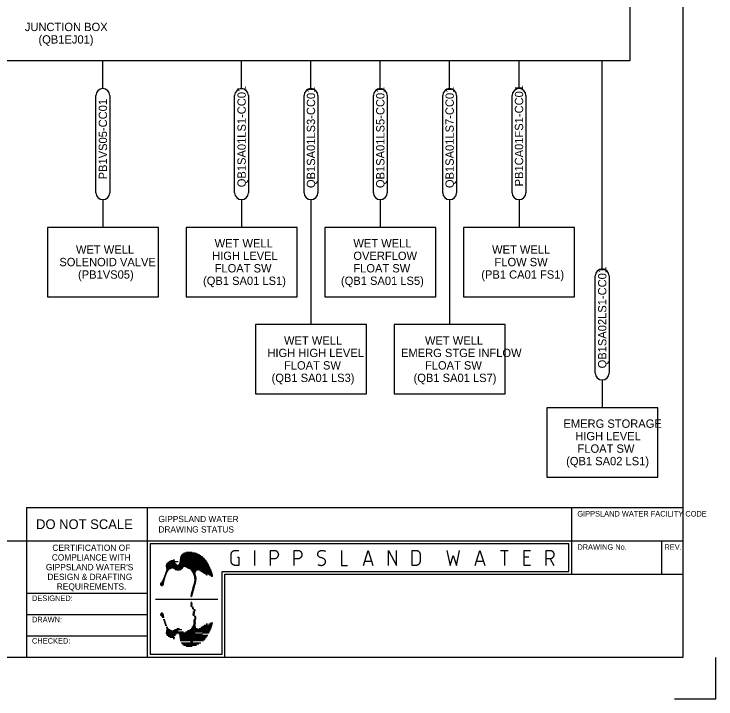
# Model space of a CAD drawing. Extents: x 0 to 841, y 0 to 594.
# Drawn here: x 588 to 841, y 0 to 246.9 of the extents above; entities that cross this region are included whole.
import ezdxf

# ---------------------------------------------------------------- set-up
doc = ezdxf.new("R2010")
doc.units = 0
doc.layers.add('A1BORDER', color=7, linetype='Continuous')
doc.layers.add('INSTALLED', color=7, linetype='Continuous')

msp = doc.modelspace()

# ---------------------------------------------------------------- linework, layer by layer
at = {"layer": 'A1BORDER'}
for p, q in [((829, 581), (829, 15)), ((592.5, 69), (592.5, 15)), ((592.5, 69), (829, 69)), ((636, 69), (636, 15)), ((789, 45), (789, 69)), ((28, 57), (829, 57)), ((637, 56), (788, 56)), ((637, 56), (637, 16)), ((788, 46), (788, 56)), ((821.5, 45), (821.5, 57)), ((647.88, 50.72), (656.5, 50.72)), ((647.91, 50.92), (656.3, 50.92)), ((647.96, 51.12), (656.08, 51.12)), ((648.03, 51.32), (655.85, 51.32)), ((648.12, 51.52), (655.59, 51.52)), ((648.23, 51.72), (655.31, 51.72)), ((648.37, 51.92), (655, 51.92)), ((648.53, 52.12), (654.64, 52.12)), ((648.74, 52.32), (654.24, 52.32)), ((649.02, 52.52), (653.76, 52.52)), ((649.39, 52.72), (653.15, 52.72)), ((650.01, 52.92), (652.2, 52.92)), ((642.73, 48.12), (658.25, 48.12)), ((642.75, 48.32), (646.79, 48.32)), ((642.81, 48.52), (646.55, 48.52)), ((642.9, 48.72), (646.37, 48.72)), ((643.04, 48.92), (646.16, 48.92)), ((643.26, 49.12), (645.9, 49.12)), ((643.54, 49.32), (645.57, 49.32)), ((643.85, 49.52), (647.09, 49.52)), ((644.18, 49.72), (645.89, 49.72)), ((644.54, 49.92), (645.36, 49.92)), ((645.37, 50.12), (645.86, 50.12)), ((647.19, 48.32), (658.14, 48.32)), ((647.42, 48.52), (658.03, 48.52)), ((647.54, 48.72), (657.92, 48.72)), ((647.61, 48.92), (657.8, 48.92)), ((647.63, 49.12), (657.68, 49.12)), ((647.66, 49.32), (657.57, 49.32)), ((647.69, 49.52), (657.44, 49.52)), ((647.71, 49.72), (657.31, 49.72)), ((647.75, 49.92), (657.17, 49.92)), ((647.78, 50.12), (657.02, 50.12)), ((647.81, 50.32), (656.86, 50.32)), ((647.85, 50.52), (656.69, 50.52)), ((642.65, 45.72), (643.2, 45.72)), ((642.72, 45.92), (643.3, 45.92)), ((642.74, 47.92), (658.35, 47.92)), ((642.79, 47.72), (649.08, 47.72)), ((642.79, 46.12), (643.4, 46.12)), ((642.83, 47.52), (648.95, 47.52)), ((642.84, 46.32), (643.5, 46.32)), ((642.85, 47.31), (644.88, 47.31)), ((642.87, 47.12), (644.57, 47.12)), ((642.87, 46.52), (643.6, 46.52)), ((642.88, 46.92), (644.23, 46.92)), ((642.88, 46.72), (643.83, 46.72)), ((645.14, 47.31), (648.83, 47.31)), ((645.49, 47.12), (648.67, 47.12)), ((645.76, 46.92), (648.42, 46.92)), ((646.05, 46.72), (648.11, 46.72)), ((646.62, 46.52), (647.67, 46.52)), ((649.72, 47.72), (658.45, 47.72)), ((650.12, 47.52), (658.55, 47.52)), ((650.48, 47.31), (658.64, 47.31)), ((650.87, 47.12), (658.73, 47.12)), ((651.36, 46.92), (658.82, 46.92)), ((651.76, 46.72), (658.9, 46.72)), ((651.88, 46.52), (654.15, 46.52)), ((651.99, 46.32), (653.71, 46.32)), ((652.1, 46.12), (653.52, 46.12)), ((652.2, 45.92), (653.4, 45.92)), ((652.31, 45.72), (653.33, 45.72)), ((654.57, 46.52), (658.99, 46.52)), ((655, 46.32), (659.07, 46.32)), ((655.31, 46.12), (659.14, 46.12)), ((655.62, 45.92), (659.22, 45.92)), ((655.93, 45.72), (659.29, 45.72)), ((663, 46), (788, 46)), ((663, 16), (663, 46)), ((641.64, 43.12), (642.25, 43.12)), ((641.73, 43.32), (642.3, 43.32)), ((641.82, 43.51), (642.35, 43.51)), ((641.91, 43.72), (642.41, 43.72)), ((641.99, 43.92), (642.48, 43.92)), ((642.06, 44.12), (642.55, 44.12)), ((642.13, 44.32), (642.62, 44.32)), ((642.21, 44.52), (642.69, 44.52)), ((642.28, 44.72), (642.76, 44.72)), ((642.35, 44.92), (642.83, 44.92)), ((642.43, 45.12), (642.9, 45.12)), ((642.5, 45.32), (643, 45.32)), ((642.57, 45.52), (643.1, 45.52)), ((652.41, 45.52), (653.31, 45.52)), ((652.5, 45.32), (653.34, 45.32)), ((652.6, 45.12), (653.38, 45.12)), ((652.69, 44.92), (653.41, 44.92)), ((652.78, 44.72), (653.44, 44.72)), ((652.83, 44.52), (653.48, 44.52)), ((652.86, 44.32), (653.53, 44.32)), ((652.89, 44.12), (653.57, 44.12)), ((652.91, 43.92), (653.62, 43.92)), ((652.94, 43.72), (653.67, 43.72)), ((652.97, 43.51), (653.71, 43.51)), ((653, 43.32), (653.69, 43.32)), ((653.02, 43.12), (653.67, 43.12)), ((656.24, 45.52), (659.35, 45.52)), ((656.55, 45.32), (659.42, 45.32)), ((656.86, 45.12), (657.74, 45.12)), ((657.17, 44.92), (657.68, 44.92)), ((657.51, 44.72), (657.54, 44.72)), ((657.91, 45.12), (659.48, 45.12)), ((658.19, 44.92), (659.54, 44.92)), ((658.47, 44.72), (659.59, 44.72)), ((658.75, 44.52), (659.58, 44.52)), ((659.02, 44.32), (659.47, 44.32)), ((664, 45), (829, 45)), ((664, 15), (664, 45)), ((640.62, 41.32), (641.88, 41.32)), ((640.63, 41.52), (641.93, 41.52)), ((640.72, 41.12), (641.73, 41.12)), ((640.73, 41.72), (641.95, 41.72)), ((640.9, 41.92), (641.97, 41.92)), ((641.03, 40.92), (641.43, 40.92)), ((641.1, 42.12), (642, 42.12)), ((641.25, 42.31), (642.04, 42.31)), ((641.37, 42.52), (642.09, 42.52)), ((641.46, 42.72), (642.15, 42.72)), ((641.55, 42.92), (642.2, 42.92)), ((652.47, 40.52), (653.1, 40.52)), ((652.52, 40.72), (653.15, 40.72)), ((652.57, 40.92), (653.2, 40.92)), ((652.63, 41.12), (653.26, 41.12)), ((652.68, 41.32), (653.31, 41.32)), ((652.74, 41.52), (653.37, 41.52)), ((652.79, 41.72), (653.41, 41.72)), ((652.85, 41.92), (653.45, 41.92)), ((652.9, 42.12), (653.49, 42.12)), ((652.95, 42.31), (653.53, 42.31)), ((652.99, 42.52), (653.57, 42.52)), ((653.03, 42.72), (653.61, 42.72)), ((653.05, 42.92), (653.64, 42.92)), ((636, 38), (592.5, 38)), ((651.82, 38.12), (652.44, 38.12)), ((651.87, 38.32), (652.5, 38.32)), ((651.92, 38.52), (652.55, 38.52)), ((651.98, 38.72), (652.61, 38.72)), ((652.03, 38.92), (652.66, 38.92)), ((652.09, 39.12), (652.72, 39.12)), ((652.14, 39.32), (652.77, 39.32)), ((652.2, 39.52), (652.82, 39.52)), ((652.25, 39.72), (652.88, 39.72)), ((652.3, 39.92), (652.93, 39.92)), ((652.36, 40.12), (652.99, 40.12)), ((652.41, 40.32), (653.04, 40.32)), ((638.93, 35.98), (661.47, 35.98)), ((651.63, 37.32), (652.23, 37.32)), ((651.64, 37.12), (652.17, 37.12)), ((651.65, 37.52), (652.28, 37.52)), ((651.71, 37.72), (652.34, 37.72)), ((651.76, 37.92), (652.39, 37.92)), ((651.79, 36.92), (651.9, 36.92)), ((651.54, 33.84), (652.17, 33.84)), ((651.63, 34.64), (652.23, 34.64)), ((651.65, 33.44), (652.28, 33.44)), ((651.71, 34.24), (652.34, 34.24)), ((651.79, 35.04), (651.9, 35.04)), ((652.03, 33.04), (652.66, 33.04)), ((640.62, 30.64), (641.88, 30.64)), ((641.03, 31.04), (641.43, 31.04)), ((652.14, 32.64), (652.77, 32.64)), ((652.34, 30.64), (652.97, 30.64)), ((652.47, 31.44), (653.1, 31.44)), ((652.57, 31.04), (653.2, 31.04)), ((652.66, 32.24), (653.29, 32.24)), ((652.77, 31.84), (653.4, 31.84)), ((636, 30.34), (592.5, 30.34)), ((640.73, 30.24), (641.95, 30.24)), ((641.1, 29.84), (642, 29.84)), ((641.37, 29.44), (642.09, 29.44)), ((641.73, 28.64), (642.3, 28.64)), ((641.91, 28.24), (642.41, 28.24)), ((642.06, 27.84), (642.55, 27.84)), ((652.45, 30.24), (653.07, 30.24)), ((652.66, 27.84), (653.35, 27.84)), ((652.72, 28.24), (653.44, 28.24)), ((652.77, 28.64), (653.46, 28.64)), ((652.9, 29.84), (653.49, 29.84)), ((652.99, 29.44), (653.57, 29.44)), ((653.05, 29.04), (653.64, 29.04)), ((642.21, 27.44), (642.69, 27.44)), ((642.35, 27.04), (642.83, 27.04)), ((642.5, 26.64), (643, 26.64)), ((642.79, 25.84), (643.4, 25.84)), ((642.87, 25.44), (643.6, 25.44)), ((646.62, 25.44), (647.67, 25.44)), ((651.88, 25.44), (654.15, 25.44)), ((652.1, 25.84), (653.52, 25.84)), ((652.31, 26.24), (653.33, 26.24)), ((652.5, 26.64), (653.34, 26.64)), ((652.69, 27.04), (653.41, 27.04)), ((652.83, 27.44), (653.48, 27.44)), ((654.57, 25.44), (658.99, 25.44)), ((655.31, 25.84), (659.14, 25.84)), ((655.93, 26.24), (659.29, 26.24)), ((656.55, 26.64), (659.42, 26.64)), ((657.17, 27.04), (657.68, 27.04)), ((658.19, 27.04), (659.54, 27.04)), ((658.75, 27.44), (659.58, 27.44)), ((642.73, 23.84), (653.27, 23.84)), ((642.79, 24.24), (649.08, 24.24)), ((642.81, 23.44), (646.55, 23.44)), ((642.85, 24.65), (644.88, 24.65)), ((642.88, 25.04), (644.23, 25.04)), ((643.04, 23.04), (646.16, 23.04)), ((645.14, 24.65), (647.18, 24.65)), ((645.76, 25.04), (648.42, 25.04)), ((647.42, 23.44), (655.89, 23.44)), ((647.61, 23.04), (657.8, 23.04)), ((649.72, 24.24), (658.45, 24.24)), ((650.48, 24.65), (658.64, 24.65)), ((651.36, 25.04), (658.82, 25.04)), ((655.94, 23.84), (658.25, 23.84)), ((636, 22.67), (592.5, 22.67)), ((643.54, 22.64), (645.57, 22.64)), ((644.18, 22.24), (645.89, 22.24)), ((645.37, 21.84), (645.86, 21.84)), ((647.66, 22.64), (657.57, 22.64)), ((647.71, 22.24), (657.31, 22.24)), ((647.78, 21.84), (657.02, 21.84)), ((647.85, 21.44), (656.69, 21.44)), ((647.91, 21.04), (656.3, 21.04)), ((651.57, 20.64), (652.44, 20.64)), ((648.23, 20.24), (655.31, 20.24)), ((648.53, 19.84), (654.64, 19.84)), ((649.02, 19.44), (653.76, 19.44)), ((650.01, 19.04), (652.2, 19.04)), ((663, 16), (637, 16)), ((829, 15), (28, 15)), ((829, 15), (829, 15)), ((841, 0), (841, 15)), ((826, 0), (841, 0))]:
    msp.add_line(p, q, dxfattribs=at)
for points in [[(668.49, 51.15), (669.06, 51.15), (669.06, 48.16), (667.64, 48.16), (667.51, 48.16), (667.39, 48.18), (667.28, 48.21), (667.15, 48.25), (667.04, 48.3), (666.93, 48.36), (666.82, 48.43), (666.73, 48.51), (666.64, 48.6), (666.55, 48.7), (666.48, 48.8), (666.41, 48.91), (666.35, 49.02), (666.31, 49.14), (666.27, 49.27), (666.24, 49.39), (666.22, 49.52), (666.22, 49.66), (666.22, 52.05), (666.22, 52.18), (666.24, 52.31), (666.27, 52.43), (666.31, 52.56), (666.35, 52.67), (666.41, 52.79), (666.48, 52.9), (666.55, 53), (666.64, 53.1), (666.73, 53.19), (666.82, 53.27), (666.93, 53.34), (667.04, 53.4), (667.15, 53.45), (667.28, 53.49), (667.39, 53.52), (667.51, 53.54), (667.64, 53.54), (669.06, 53.54)], [(674.74, 48.16), (674.74, 53.54)], [(680.42, 48.16), (680.42, 53.54), (681.84, 53.54), (681.96, 53.54), (682.08, 53.52), (682.2, 53.49), (682.32, 53.45), (682.43, 53.4), (682.54, 53.34), (682.65, 53.27), (682.74, 53.19), (682.84, 53.1), (682.92, 53), (682.99, 52.9), (683.06, 52.79), (683.12, 52.67), (683.17, 52.56), (683.21, 52.43), (683.23, 52.31), (683.25, 52.18), (683.26, 52.05), (683.25, 51.91), (683.23, 51.78), (683.21, 51.66), (683.17, 51.53), (683.12, 51.42), (683.06, 51.3), (682.99, 51.19), (682.92, 51.09), (682.84, 50.99), (682.74, 50.9), (682.65, 50.82), (682.54, 50.75), (682.43, 50.69), (682.32, 50.64), (682.2, 50.6), (682.08, 50.57), (681.96, 50.55), (681.84, 50.55), (680.42, 50.55)], [(688.93, 48.16), (688.93, 53.54), (690.35, 53.54), (690.47, 53.54), (690.59, 53.52), (690.71, 53.49), (690.83, 53.45), (690.94, 53.4), (691.05, 53.34), (691.16, 53.27), (691.26, 53.19), (691.35, 53.1), (691.43, 53), (691.51, 52.9), (691.57, 52.79), (691.63, 52.67), (691.68, 52.56), (691.72, 52.43), (691.75, 52.31), (691.76, 52.18), (691.77, 52.05), (691.76, 51.91), (691.75, 51.78), (691.72, 51.66), (691.68, 51.53), (691.63, 51.42), (691.57, 51.3), (691.51, 51.19), (691.43, 51.09), (691.35, 50.99), (691.26, 50.9), (691.16, 50.82), (691.05, 50.75), (690.94, 50.69), (690.83, 50.64), (690.71, 50.6), (690.59, 50.57), (690.47, 50.55), (690.35, 50.55), (688.93, 50.55)], [(697.45, 48.46), (697.67, 48.36), (697.9, 48.27), (698.12, 48.21), (698.36, 48.17), (698.6, 48.16), (698.84, 48.16), (698.87, 48.16), (699.03, 48.18), (699.18, 48.21), (699.33, 48.26), (699.48, 48.32), (699.62, 48.4), (699.72, 48.46), (699.81, 48.53), (699.9, 48.61), (699.98, 48.69), (700.05, 48.78), (700.11, 48.88), (700.17, 48.99), (700.22, 49.09), (700.25, 49.21), (700.28, 49.32), (700.29, 49.36), (700.3, 49.44), (700.3, 49.52), (700.3, 49.61), (700.29, 49.69), (700.27, 49.77), (700.25, 49.86), (700.22, 49.93), (700.18, 50.01), (700.14, 50.09), (700.09, 50.15), (700.04, 50.21), (700.01, 50.25), (699.85, 50.39), (699.69, 50.51), (699.52, 50.61), (699.34, 50.7), (699.15, 50.78), (698.95, 50.83), (698.87, 50.85), (698.68, 50.9), (698.49, 50.96), (698.3, 51.04), (698.12, 51.14), (697.96, 51.26), (697.8, 51.39), (697.73, 51.45), (697.67, 51.51), (697.62, 51.57), (697.58, 51.64), (697.53, 51.71), (697.5, 51.79), (697.47, 51.87), (697.46, 51.95), (697.44, 52.04), (697.43, 52.12), (697.43, 52.21), (697.44, 52.29), (697.45, 52.35), (697.47, 52.46), (697.51, 52.58), (697.55, 52.69), (697.61, 52.79), (697.67, 52.89), (697.74, 52.99), (697.82, 53.07), (697.9, 53.15), (697.99, 53.23), (698.02, 53.24), (698.15, 53.33), (698.3, 53.4), (698.44, 53.45), (698.6, 53.5), (698.75, 53.52), (698.87, 53.54), (699.11, 53.55), (699.35, 53.53), (699.58, 53.49), (699.82, 53.43), (700.04, 53.35), (700.27, 53.25)], [(705.96, 53.54), (705.96, 48.16), (708.23, 48.16)], [(713.91, 48.16), (715.61, 53.54), (717.32, 48.16)], [(722.99, 48.16), (722.99, 53.54), (725.83, 48.16), (725.83, 53.54)], [(731.52, 48.16), (731.52, 53.54), (732.94, 53.54), (733.06, 53.54), (733.18, 53.52), (733.3, 53.49), (733.42, 53.45), (733.53, 53.4), (733.64, 53.34), (733.75, 53.27), (733.84, 53.19), (733.94, 53.1), (734.02, 53), (734.09, 52.9), (734.16, 52.79), (734.22, 52.67), (734.27, 52.56), (734.31, 52.43), (734.33, 52.31), (734.35, 52.18), (734.36, 52.05), (734.36, 49.66), (734.35, 49.52), (734.33, 49.39), (734.31, 49.27), (734.27, 49.14), (734.22, 49.02), (734.16, 48.91), (734.09, 48.8), (734.02, 48.7), (733.94, 48.6), (733.84, 48.51), (733.75, 48.43), (733.64, 48.36), (733.53, 48.3), (733.42, 48.25), (733.3, 48.21), (733.18, 48.18), (733.06, 48.16), (732.94, 48.16), (731.52, 48.16)], [(744.01, 53.54), (745.14, 48.16), (746.28, 51.75), (747.41, 48.16), (748.55, 53.54)], [(754.22, 48.16), (755.92, 53.54), (757.63, 48.16)], [(763.31, 53.54), (766.15, 53.54)], [(764.73, 53.54), (764.73, 48.16)], [(774.09, 48.16), (771.82, 48.16), (771.82, 53.54), (774.09, 53.54)], [(779.78, 48.16), (779.78, 53.54), (781.2, 53.54), (781.32, 53.54), (781.44, 53.52), (781.56, 53.49), (781.68, 53.45), (781.79, 53.4), (781.9, 53.34), (782.01, 53.27), (782.1, 53.19), (782.2, 53.1), (782.28, 53), (782.35, 52.9), (782.42, 52.79), (782.48, 52.67), (782.53, 52.56), (782.56, 52.43), (782.59, 52.31), (782.61, 52.18), (782.61, 52.05), (782.61, 51.91), (782.59, 51.78), (782.56, 51.66), (782.53, 51.53), (782.48, 51.42), (782.42, 51.3), (782.35, 51.19), (782.28, 51.09), (782.2, 50.99), (782.1, 50.9), (782.01, 50.82), (781.9, 50.75), (781.79, 50.69), (781.68, 50.64), (781.56, 50.6), (781.44, 50.57), (781.32, 50.55), (781.2, 50.55), (779.78, 50.55)], [(773.53, 51.15), (771.82, 51.15)], [(714.48, 49.66), (716.75, 49.66)], [(754.79, 49.66), (757.06, 49.66)], [(781.2, 50.55), (782.61, 48.16)]]:
    msp.add_lwpolyline(points, dxfattribs=at)
at = {"layer": 'INSTALLED'}
for p, q in [((620, 220), (620, 230)), ((670, 220), (670, 230)), ((695, 220), (695, 230)), ((720, 220), (720, 230)), ((745, 220), (745, 230)), ((770, 220), (770, 230)), ((800, 155), (800, 230)), ((617.5, 182.5), (617.5, 217.5)), ((622.5, 217.5), (622.5, 182.5)), ((667.5, 182.5), (667.5, 217.5)), ((672.5, 217.5), (672.5, 182.5)), ((692.5, 182.5), (692.5, 217.5)), ((697.5, 217.5), (697.5, 182.5)), ((717.5, 182.5), (717.5, 217.5)), ((722.5, 217.5), (722.5, 182.5)), ((742.5, 182.5), (742.5, 217.5)), ((747.5, 217.5), (747.5, 182.5)), ((767.5, 182.5), (767.5, 217.5)), ((772.5, 217.5), (772.5, 182.5)), ((620, 180), (620, 170)), ((670, 180), (670, 170)), ((695, 180), (695, 135)), ((720, 180), (720, 170)), ((745, 180), (745, 135)), ((770, 180), (770, 170)), ((797.5, 117.5), (797.5, 152.5)), ((802.5, 152.5), (802.5, 117.5)), ((800, 115), (800, 105))]:
    msp.add_line(p, q, dxfattribs=at)
for points in [[(400, 230), (400, 250), (810, 250), (810, 230)], [(600, 145), (640, 145), (640, 170), (600, 170)], [(650, 145), (690, 145), (690, 170), (650, 170)], [(700, 145), (740, 145), (740, 170), (700, 170)], [(750, 145), (790, 145), (790, 170), (750, 170)], [(675, 110), (715, 110), (715, 135), (675, 135)], [(725, 110), (765, 110), (765, 135), (725, 135)], [(780, 80), (820, 80), (820, 105), (780, 105)]]:
    msp.add_lwpolyline(points, close=True, dxfattribs=at)
for centre, start, end in [((620, 217.5), 0, 180), ((670, 217.5), 0, 180), ((695, 217.5), 0, 180), ((720, 217.5), 0, 180), ((745, 217.5), 0, 180), ((770, 217.5), 0, 180), ((620, 182.5), 180, 0), ((670, 182.5), 180, 0), ((695, 182.5), 180, 0), ((720, 182.5), 180, 0), ((745, 182.5), 180, 0), ((770, 182.5), 180, 0), ((800, 152.5), 0, 180), ((800, 117.5), 180, 0)]:
    msp.add_arc(centre, 2.5, start, end, dxfattribs=at)

# ---------------------------------------------------------------- texts
at = {"layer": 'A1BORDER'}
for s, height, p in [('GIPPSLAND WATER', 2.25, (640, 63.75)), ('GIPPSLAND WATER FACILITY CODE', 2, (791.03, 65.77)), ('DO NOT SCALE', 3.5, (595.92, 61.25)), ('DRAWING STATUS', 2.25, (640, 60)), ('CERTIFICATION OF', 2.25, (601.79, 53.39)), ('DRAWING No.', 2, (791.03, 53.77)), ('REV.', 2, (822.43, 53.77)), ('COMPLIANCE WITH', 2.25, (601.57, 49.89)), ("GIPPSLAND WATER'S", 2.25, (599.45, 46.39)), ('DESIGN & DRAFTING', 2.25, (600, 42.89)), ('REQUIREMENTS.', 2.25, (603.37, 39.39)), ('DESIGNED:', 2, (594.44, 35.29)), ('DRAWN:', 2, (594.44, 27.62)), ('CHECKED:', 2, (594.44, 19.95))]:
    msp.add_text(s, height=height, dxfattribs=at).set_placement(p)
at = {"layer": 'INSTALLED'}
for s, rotation, p in [('JUNCTION BOX', 360, (591.85, 240.75)), ('(QB1EJ01)', 360, (596.78, 236.25)), ('QB1SA01LS1-CC01', 90, (671.5, 184.46)), ('QB1SA01LS3-CC01', 90, (696.5, 184.16)), ('QB1SA01LS5-CC01', 90, (721.5, 184.16)), ('QB1SA01LS7-CC01', 90, (746.5, 184.16)), ('PB1CA01FS1-CC01', 90, (771.5, 184.76)), ('PB1VS05-CC01', 90, (621.5, 187.3)), ('QB1SA02LS1-CC01', 90, (801.5, 119.16))]:
    msp.add_text(s, height=3, rotation=rotation, dxfattribs=at).set_placement(p)
for s, p in [('WET WELL', (660.29, 162.75)), ('WET WELL', (710.29, 162.75)), ('WET WELL', (610.29, 160.5)), ('WET WELL', (760.29, 160.5)), ('HIGH LEVEL', (659.39, 158.25)), ('OVERFLOW', (710.29, 158.25)), ('SOLENOID VALVE', (604.31, 156)), ('FLOW SW', (761.18, 156)), ('(PB1VS05)', (611.04, 151.5)), ('FLOAT SW', (660.29, 153.75)), ('FLOAT SW', (710.29, 153.75)), ('(PB1 CA01 FS1)', (756.4, 151.5)), ('(QB1 SA01 LS1)', (656.1, 149.25)), ('(QB1 SA01 LS5)', (705.81, 149.25)), ('WET WELL', (685.29, 127.75)), ('WET WELL', (736.1, 127.75)), ('HIGH HIGH LEVEL', (679.31, 123.25)), ('EMERG STGE INFLOW', (727.47, 123.25)), ('FLOAT SW', (685.29, 118.75)), ('FLOAT SW', (736.1, 118.75)), ('(QB1 SA01 LS3)', (680.81, 114.25)), ('(QB1 SA01 LS7)', (731.99, 114.25)), ('EMERG STORAGE', (786.03, 97.75)), ('HIGH LEVEL', (790.28, 93.25)), ('FLOAT SW', (791.1, 88.75)), ('(QB1 SA02 LS1)', (786.99, 84.25))]:
    msp.add_text(s, height=3, dxfattribs=at).set_placement(p)

doc.saveas('drawing.dxf')
